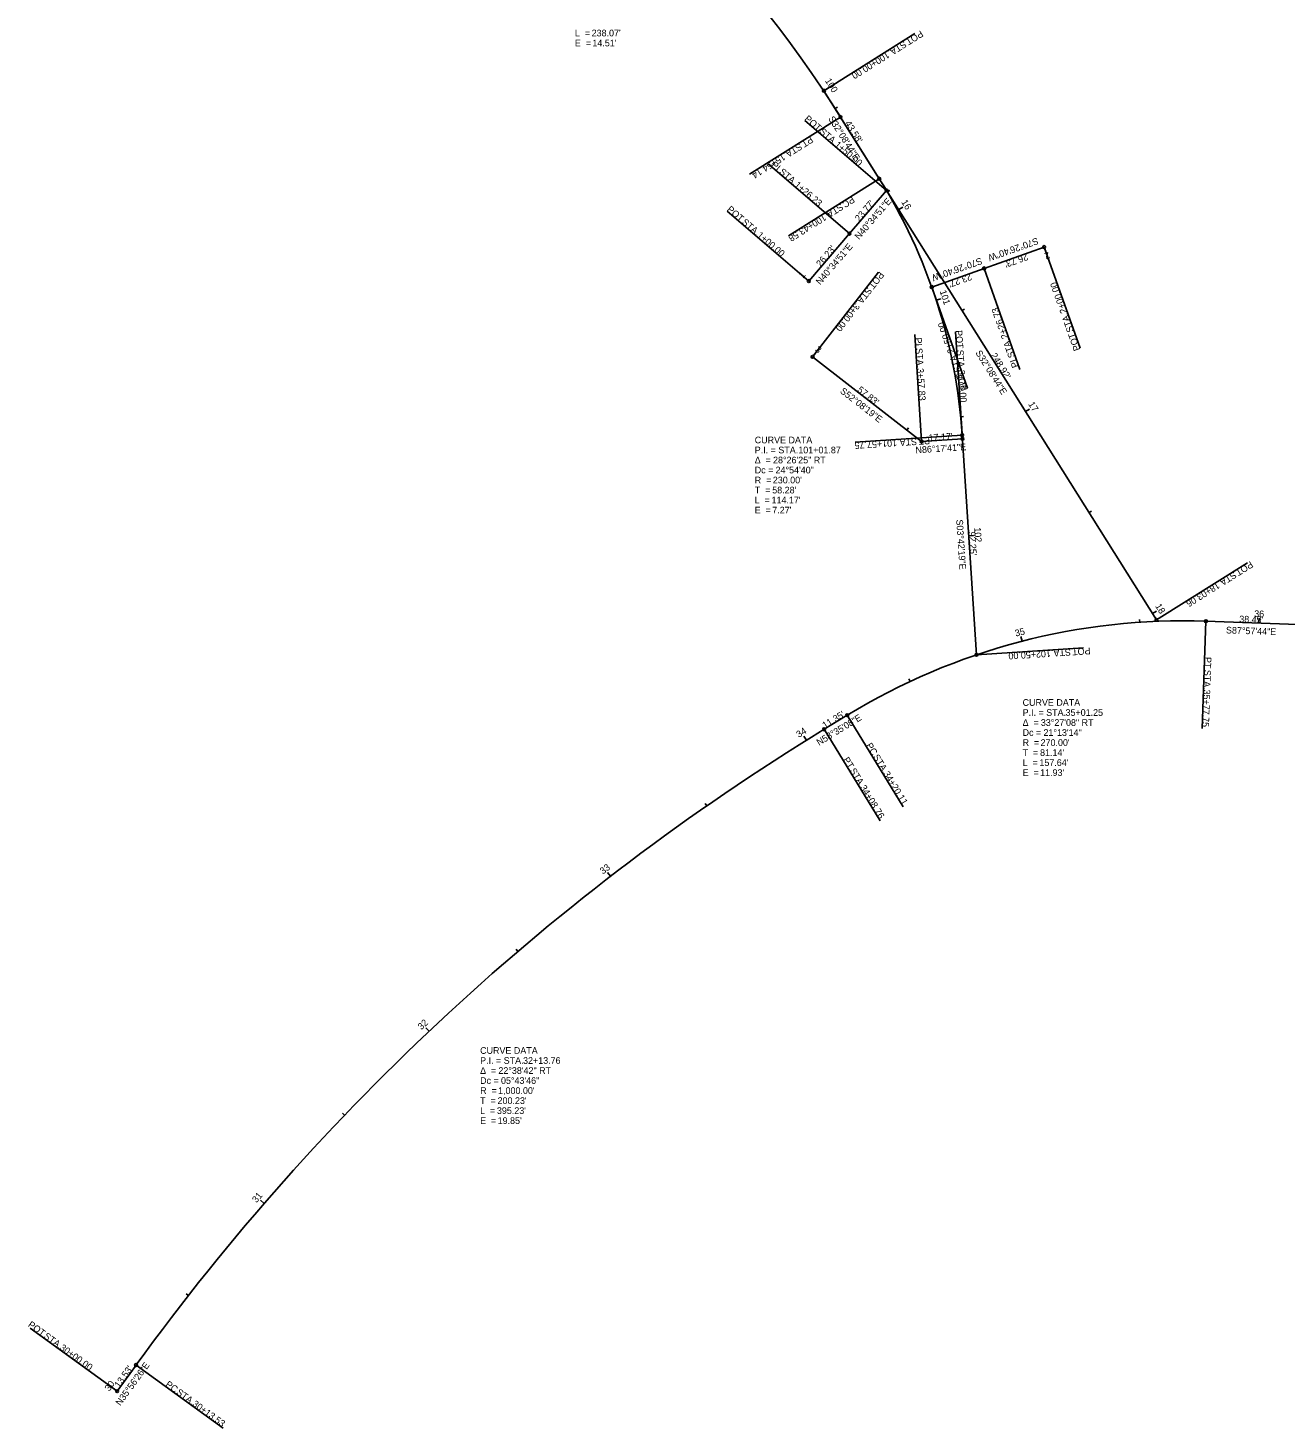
# Model space of a CAD drawing. Extents: x 1927094 to 1928117, y 199395 to 200287.
# Drawn here: x 1927208 to 1927736, y 199395 to 199982 of the extents above; entities that cross this region are included whole.
import ezdxf

# ---------------------------------------------------------------- set-up
doc = ezdxf.new("R2010")
doc.units = 0
for name, color, linetype in [('GE_P_Alignment', 7, 'Continuous'), ('GE_P_Alignment_100_Bearings', 7, 'Continuous'), ('GE_P_Alignment_100_Cardinal_Points', 7, 'Continuous'), ('GE_P_Alignment_100_Curve_Data', 7, 'Continuous'), ('GE_P_Alignment_100_Distances', 7, 'Continuous'), ('GE_P_Alignment_100_Stations', 7, 'Continuous'), ('GE_P_Driveway_CL', 7, 'Continuous'), ('GE_X_Alignment', 7, 'Continuous'), ('GE_X_Alignment_100_Bearings', 7, 'Continuous'), ('GE_X_Alignment_100_Cardinal_Points', 7, 'Continuous'), ('GE_X_Alignment_100_Curve_Data', 7, 'Continuous'), ('GE_X_Alignment_100_Distances', 7, 'Continuous'), ('GE_X_Alignment_100_Stations', 7, 'Continuous')]:
    doc.layers.add(name, color=color, linetype=linetype)

msp = doc.modelspace()

# ---------------------------------------------------------------- linework, layer by layer
at = {"layer": 'GE_P_Alignment'}
for p, q in [((1927541.94, 199955.28), (1927565.13, 199918.38)), ((1927599.9, 199810.87), (1927605.87, 199718.81))]:
    msp.add_line(p, q, dxfattribs=at)
msp.add_arc((1927370.38, 199796.01), 230, 3.70523, 32.14552, dxfattribs=at)
at = {"layer": 'GE_P_Alignment_100_Cardinal_Points'}
for p, q in [((1927541.94, 199955.28), (1927580.04, 199979.23)), ((1927568.14, 199913.44), (1927533.96, 199942.72)), ((1927552.68, 199895.39), (1927518.5, 199924.66)), ((1927565.13, 199918.38), (1927527.02, 199894.44)), ((1927535.62, 199875.47), (1927501.44, 199904.74)), ((1927634.23, 199889.73), (1927649.3, 199847.32)), ((1927537.21, 199843.7), (1927564.83, 199879.23)), ((1927609.04, 199880.78), (1927624.1, 199838.37)), ((1927587.12, 199872.99), (1927602.18, 199830.59)), ((1927600, 199809.31), (1927597.1, 199854.22)), ((1927582.87, 199808.2), (1927579.97, 199853.11)), ((1927599.9, 199810.87), (1927555, 199807.96)), ((1927605.87, 199718.81), (1927650.77, 199721.72))]:
    msp.add_line(p, q, dxfattribs=at)
for centre in [(1927541.94, 199955.28), (1927565.13, 199918.38), (1927568.14, 199913.44), (1927552.68, 199895.39), (1927634.23, 199889.73), (1927609.04, 199880.78), (1927535.62, 199875.47), (1927587.12, 199872.99), (1927537.21, 199843.7), (1927582.87, 199808.2), (1927599.9, 199810.87), (1927600, 199809.31), (1927605.87, 199718.81)]:
    msp.add_circle(centre, 0.6, dxfattribs=at)
at = {"layer": 'GE_P_Alignment_100_Stations'}
for p, q in [((1927541.94, 199955.28), (1927543.63, 199956.35)), ((1927568.14, 199913.44), (1927567.23, 199914.23)), ((1927568.46, 199912.9), (1927569.5, 199913.51)), ((1927634.23, 199889.73), (1927634.9, 199887.84)), ((1927535.62, 199875.47), (1927534.1, 199876.77)), ((1927587.12, 199872.99), (1927587.52, 199871.86)), ((1927589.01, 199867.43), (1927590.91, 199868.05)), ((1927537.21, 199843.7), (1927538.44, 199845.28)), ((1927599.27, 199818.59), (1927600.47, 199818.71)), ((1927576.69, 199813.01), (1927577.43, 199813.96)), ((1927602.63, 199768.71), (1927604.63, 199768.84)), ((1927605.87, 199718.81), (1927607.06, 199718.89))]:
    msp.add_line(p, q, dxfattribs=at)
at = {"layer": 'GE_P_Driveway_CL'}
for p, q in [((1927552.68, 199895.39), (1927568.14, 199913.44)), ((1927535.62, 199875.47), (1927552.68, 199895.39)), ((1927634.23, 199889.73), (1927609.04, 199880.78)), ((1927609.04, 199880.78), (1927587.12, 199872.99)), ((1927537.21, 199843.7), (1927582.87, 199808.2)), ((1927582.87, 199808.2), (1927600, 199809.31))]:
    msp.add_line(p, q, dxfattribs=at)
at = {"layer": 'GE_X_Alignment'}
for p, q in [((1927548.87, 199944.25), (1927681.31, 199733.49)), ((1927702.05, 199732.9), (1927740.52, 199731.53)), ((1927542.03, 199687.58), (1927551.72, 199693.49)), ((1927245.69, 199410.15), (1927253.63, 199421.1))]:
    msp.add_line(p, q, dxfattribs=at)
for centre, radius, start, end in [((1927125.52, 199678.22), 500, 32.14552, 59.42679), ((1927692.45, 199463.07), 270, 87.9622, 121.4145), ((1928063.26, 198834.16), 1000, 121.4145, 144.05937)]:
    msp.add_arc(centre, radius, start, end, dxfattribs=at)
at = {"layer": 'GE_X_Alignment_100_Cardinal_Points'}
for p, q in [((1927548.87, 199944.25), (1927510.77, 199920.31)), ((1927681.31, 199733.49), (1927719.41, 199757.43)), ((1927702.05, 199732.9), (1927700.45, 199687.93)), ((1927551.72, 199693.49), (1927575.18, 199655.09)), ((1927542.03, 199687.58), (1927565.49, 199649.17)), ((1927245.69, 199410.15), (1927209.26, 199436.56)), ((1927253.63, 199421.1), (1927290.07, 199394.69))]:
    msp.add_line(p, q, dxfattribs=at)
for centre in [(1927548.87, 199944.25), (1927681.31, 199733.49), (1927702.05, 199732.9), (1927551.72, 199693.49), (1927542.03, 199687.58), (1927253.63, 199421.1), (1927245.69, 199410.15)]:
    msp.add_circle(centre, 0.6, dxfattribs=at)
at = {"layer": 'GE_X_Alignment_100_Stations'}
for p, q in [((1927546.65, 199947.75), (1927547.66, 199948.39)), ((1927573.27, 199905.42), (1927574.96, 199906.48)), ((1927599.87, 199863.09), (1927600.89, 199863.72)), ((1927626.48, 199820.75), (1927628.17, 199821.81)), ((1927653.08, 199778.42), (1927654.1, 199779.05)), ((1927679.68, 199736.08), (1927681.38, 199737.14)), ((1927674.32, 199732.46), (1927674.24, 199733.66)), ((1927724.29, 199732.11), (1927724.36, 199734.11)), ((1927625.03, 199724.52), (1927624.53, 199726.45)), ((1927578.04, 199707.63), (1927577.53, 199708.72)), ((1927534.58, 199682.98), (1927533.52, 199684.68)), ((1927492.82, 199655.5), (1927492.13, 199656.48)), ((1927452.48, 199625.96), (1927451.26, 199627.54)), ((1927413.67, 199594.44), (1927412.89, 199595.36)), ((1927376.49, 199561.03), (1927375.11, 199562.48)), ((1927341.02, 199525.79), (1927340.15, 199526.62)), ((1927307.35, 199488.83), (1927305.84, 199490.14)), ((1927275.57, 199450.23), (1927274.63, 199450.97)), ((1927245.69, 199410.15), (1927244.07, 199411.32))]:
    msp.add_line(p, q, dxfattribs=at)

# ---------------------------------------------------------------- texts
at = {"layer": 'GE_P_Alignment_100_Bearings'}
for s, rotation, p in [('S32°08\'44"E', 302.14552, (1927543.65, 199943.54)), ('N40°34\'51"E', 49.4193, (1927556.66, 199892.66)), ('N40°34\'51"E', 49.4193, (1927540.4, 199873.68)), ('S70°26\'40"W', 199.55547, (1927631.24, 199893.76)), ('S70°26\'40"W', 199.55547, (1927607.68, 199885.39)), ('S52°08\'19"E', 322.13862, (1927548.46, 199828.88)), ('N86°17\'41"E', 3.70523, (1927580.41, 199803.23)), ('S03°42\'19"E', 273.70523, (1927597.39, 199775.44))]:
    msp.add_text(s, height=2.8, rotation=rotation, dxfattribs=at).set_placement(p)
at = {"layer": 'GE_P_Alignment_100_Cardinal_Points'}
for s, rotation, p in [('POT', 212.14552, (1927582.43, 199980.68)), ('100+00.00', 212.14552, (1927568.33, 199971.82)), (' STA. ', 212.14552, (1927576.33, 199976.85)), ('POT', 319.4193, (1927533.56, 199943.12)), (' STA. ', 319.4193, (1927539.03, 199938.43)), ('1+50.00', 319.4193, (1927546.21, 199932.28)), ('PI', 319.4193, (1927519.6, 199923.77)), (' STA. ', 319.4193, (1927522.18, 199921.57)), ('1+26.23', 319.4193, (1927529.36, 199915.42)), ('POT', 319.4193, (1927501.04, 199905.14)), (' STA. ', 212.14552, (1927549.82, 199908.71)), ('PC', 212.14552, (1927553.7, 199911.15)), (' STA. ', 319.4193, (1927506.51, 199900.46)), ('100+43.58', 212.14552, (1927541.81, 199903.68)), ('1+00.00', 319.4193, (1927513.68, 199894.31)), ('POT', 232.13862, (1927565.21, 199879.65)), (' STA. ', 232.13862, (1927560.79, 199873.96)), ('2+00.00', 109.55547, (1927643.87, 199862.47)), ('3+00.00', 232.13862, (1927554.99, 199866.5)), ('2+26.73', 109.55547, (1927619.29, 199851.8)), (' STA. ', 109.55547, (1927647.03, 199853.56)), ('2+50.00', 109.55547, (1927596.76, 199845.73)), ('POT', 273.70523, (1927597.1, 199854.78)), ('PI', 273.70523, (1927580.1, 199851.7)), (' STA. ', 109.55547, (1927622.46, 199842.89)), ('POT', 109.55547, (1927649.44, 199846.78)), (' STA. ', 273.70523, (1927580.32, 199848.32)), (' STA. ', 109.55547, (1927599.92, 199836.83)), (' STA. ', 273.70523, (1927597.57, 199847.6)), ('PI', 109.55547, (1927623.59, 199839.69)), ('3+57.83', 273.70523, (1927580.93, 199838.88)), ('POT', 109.55547, (1927602.33, 199830.04)), ('3+75.00', 273.70523, (1927598.18, 199838.17)), ('101+57.75', 183.70523, (1927572.46, 199809.05)), (' STA. ', 183.70523, (1927581.89, 199809.66)), ('PT', 183.70523, (1927586.3, 199809.95)), ('102+50.00', 183.70523, (1927636.95, 199720.78)), (' STA. ', 183.70523, (1927646.38, 199721.39)), ('POT', 183.70523, (1927653.57, 199721.86))]:
    msp.add_text(s, height=2.8, rotation=rotation, dxfattribs=at).set_placement(p)
at = {"layer": 'GE_P_Alignment_100_Curve_Data'}
for s, p in [('CURVE DATA', (1927512.94, 199807.46)), ('Δ  = ', (1927512.94, 199799.06)), ('P.I. = STA. ', (1927512.94, 199803.26)), ('28°26\'25" RT', (1927520.61, 199799.06)), ('101+01.87', (1927531.2, 199803.26)), ('Dc = ', (1927512.94, 199794.86)), ('24°54\'40"', (1927521.67, 199794.86)), ('T  = ', (1927512.94, 199786.46)), ('R  = ', (1927512.94, 199790.66)), ("58.28'", (1927520.27, 199786.46)), ("230.00'", (1927520.52, 199790.66)), ('L  = ', (1927512.94, 199782.26)), ("114.17'", (1927519.98, 199782.26)), ('E  = ', (1927512.94, 199778.06)), ("7.27'", (1927520.28, 199778.06))]:
    msp.add_text(s, height=2.8, dxfattribs=at).set_placement(p)
at = {"layer": 'GE_P_Alignment_100_Distances'}
for s, rotation, p in [("43.58'", 302.14552, (1927550.61, 199941.56)), ("23.77'", 49.4193, (1927556.76, 199900.22)), ("26.23'", 49.4193, (1927540.5, 199881.23)), ("26.73'", 199.55547, (1927626.89, 199887.07)), ("23.27'", 199.55547, (1927603.33, 199878.71)), ("57.83'", 322.13862, (1927555.68, 199829.4)), ("17.17'", 3.70523, (1927585.89, 199808.42)), ("92.25'", 273.70523, (1927602.57, 199770.39))]:
    msp.add_text(s, height=2.8, rotation=rotation, dxfattribs=at).set_placement(p)
at = {"layer": 'GE_P_Alignment_100_Stations'}
for s, rotation, p in [('100', 302.14552, (1927542.27, 199959.45)), ('2', 199.55547, (1927636.05, 199887.72)), ('1', 49.4193, (1927533.12, 199876.4)), ('101', 288.09166, (1927590.41, 199871.2)), ('3', 322.13862, (1927537.93, 199846.31)), ('102', 273.70523, (1927604.92, 199772.14))]:
    msp.add_text(s, height=2.8, rotation=rotation, dxfattribs=at).set_placement(p)
at = {"layer": 'GE_X_Alignment_100_Bearings'}
for s, rotation, p in [('S32°08\'44"E', 302.14552, (1927605.33, 199845.38)), ('S87°57\'44"E', 357.9622, (1927710.42, 199727.8)), ('N58°35\'08"E', 31.4145, (1927539.89, 199680.64)), ('N35°56\'26"E', 54.05937, (1927247.03, 199403.81))]:
    msp.add_text(s, height=2.8, rotation=rotation, dxfattribs=at).set_placement(p)
at = {"layer": 'GE_X_Alignment_100_Cardinal_Points'}
for s, rotation, p in [('PT', 212.14552, (1927536.28, 199936.3)), (' STA. ', 212.14552, (1927532.59, 199933.98)), ('15+54.14', 212.14552, (1927524.7, 199929.02)), (' STA. ', 212.14552, (1927714.64, 199754.39)), ('POT', 212.14552, (1927720.68, 199758.18)), ('18+03.06', 212.14552, (1927706.75, 199749.43)), ('PT', 267.9622, (1927701.56, 199717.94)), (' STA. ', 267.9622, (1927701.4, 199713.59)), ('35+77.75', 267.9622, (1927701.07, 199704.28)), ('PC', 301.4145, (1927559.48, 199680.86)), ('PT', 301.4145, (1927549.84, 199674.86)), (' STA. ', 301.4145, (1927561.88, 199676.93)), (' STA. ', 301.4145, (1927552.11, 199671.15)), ('34+20.11', 301.4145, (1927566.74, 199668.98)), ('34+08.76', 301.4145, (1927556.97, 199663.19)), ('POT', 324.05937, (1927208.08, 199437.46)), (' STA. ', 324.05937, (1927213.85, 199433.28)), ('30+00.00', 324.05937, (1927221.4, 199427.81)), ('PC', 324.05937, (1927265.68, 199412.42)), (' STA. ', 324.05937, (1927269.4, 199409.72)), ('30+13.53', 324.05937, (1927276.95, 199404.25))]:
    msp.add_text(s, height=2.8, rotation=rotation, dxfattribs=at).set_placement(p)
at = {"layer": 'GE_X_Alignment_100_Curve_Data'}
for s, p in [('L  = ', (1927437.55, 199978.06)), ("238.07'", (1927444.58, 199978.06)), ('E  = ', (1927437.55, 199973.86)), ("14.51'", (1927444.89, 199973.86)), ('CURVE DATA', (1927625.21, 199697.42)), ('P.I. = STA. ', (1927625.21, 199693.22)), ('35+01.25', (1927643.2, 199693.22)), ('Δ  = ', (1927625.21, 199689.02)), ('33°27\'08" RT', (1927632.86, 199689.02)), ('Dc = ', (1927625.21, 199684.82)), ('R  = ', (1927625.21, 199680.62)), ("270.00'", (1927632.75, 199680.62)), ('21°13\'14"', (1927633.96, 199684.82)), ('T  = ', (1927625.21, 199676.42)), ("81.14'", (1927632.53, 199676.42)), ('L  = ', (1927625.21, 199672.22)), ("157.64'", (1927632.25, 199672.22)), ('E  = ', (1927625.21, 199668.02)), ("11.93'", (1927632.56, 199668.02)), ('CURVE DATA', (1927397.83, 199551.54)), ('P.I. = STA. ', (1927397.83, 199547.34)), ('32+13.76', (1927415.83, 199547.34)), ('Δ  = ', (1927397.83, 199543.14)), ('22°38\'42" RT', (1927405.48, 199543.14)), ('Dc = ', (1927397.83, 199538.94)), ('R  = ', (1927397.83, 199534.74)), ("1,000.00'", (1927405.37, 199534.74)), ('05°43\'46"', (1927406.58, 199538.94)), ('T  = ', (1927397.83, 199530.54)), ("200.23'", (1927405.15, 199530.54)), ('L  = ', (1927397.83, 199526.34)), ('E  = ', (1927397.83, 199522.14)), ("395.23'", (1927404.87, 199526.34)), ("19.85'", (1927405.18, 199522.14))]:
    msp.add_text(s, height=2.8, dxfattribs=at).set_placement(p)
at = {"layer": 'GE_X_Alignment_100_Distances'}
for s, rotation, p in [("248.92'", 302.14552, (1927611.7, 199844.34)), ("38.49'", 357.9622, (1927715.97, 199732.44)), ("11.35'", 31.4145, (1927542.32, 199687.79)), ("13.53'", 54.05937, (1927246.51, 199411.34))]:
    msp.add_text(s, height=2.8, rotation=rotation, dxfattribs=at).set_placement(p)
at = {"layer": 'GE_X_Alignment_100_Stations'}
for s, rotation, p in [('16', 302.14552, (1927574.25, 199908.56)), ('17', 302.14552, (1927627.46, 199823.88)), ('18', 302.14552, (1927680.67, 199739.22)), ('36', 357.9622, (1927722.24, 199734.68)), ('35', 14.4611, (1927622.38, 199726.41)), ('34', 31.91622, (1927531.42, 199683.96)), ('33', 37.64579, (1927449.31, 199626.67)), ('32', 43.37537, (1927373.25, 199561.41)), ('31', 49.10495, (1927304.08, 199488.88)), ('30', 54.05937, (1927242.41, 199409.88))]:
    msp.add_text(s, height=2.8, rotation=rotation, dxfattribs=at).set_placement(p)

doc.saveas('drawing.dxf')
